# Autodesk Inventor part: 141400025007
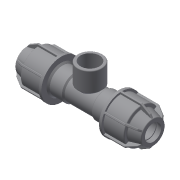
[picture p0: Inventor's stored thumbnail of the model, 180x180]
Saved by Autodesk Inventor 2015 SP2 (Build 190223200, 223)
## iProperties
Created: 2017-08
Part Number: 141400025007
Material: Generic
Description: PLASSON L.14 TEE FEMALE ADAPTOR (SILVER) 25 x 3/4" x 25
Document SubType Name: Modeling
Designer: KIM
Density: 1 g/cm^3
Appearance: Default
Author: KIM
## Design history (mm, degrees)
derived "141400.ipt"
feature "Solid1::141400.ipt"
feature "Solid2::141400.ipt"
tag "TaggingFeature1"
body "Solid1"
other parameters: "d1" = 25, "d2" = 48, "d4" = 15 deg, "d5" = 31.68, "d6" = 10.4544, "d16" = 25.5, "d17" = 2.4, "d24" = 2.4, "d25" = 45, "d26" = 37.5, "d27" = 2.4, "d28" = 135 deg, "d29" = 1.44, "d31" = 1.25, "d46" = 150 deg, "d49" = 2.5, "d50" = 0, "d58" = 0.75, "d61" = 360 deg, "d63" = 22.5, "d64" = 61.5, "d80" = 36, "d81" = 2, "d84" = 2.4, "d94" = 48, "d95" = 24.117, "d96" = 31.3521, "d97" = 19, "d98" = 22.5, "d99" = 28.21689, "d100" = 135 deg, "d108" = 1.25, "d111" = 0, "d_" = 25, "G_" = 24.117, "H_" = 123, "l_" = 48, "l_2" = 19, "A_" = 48
